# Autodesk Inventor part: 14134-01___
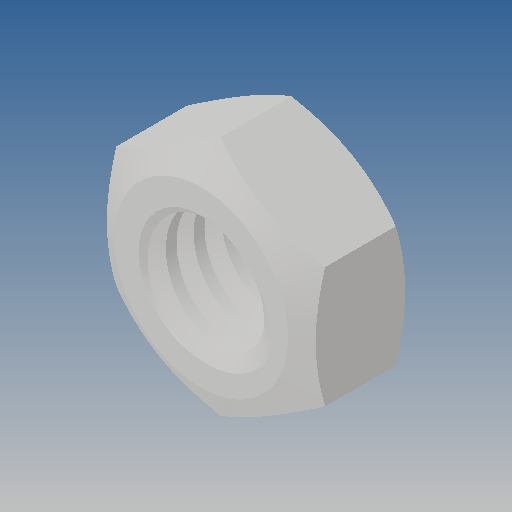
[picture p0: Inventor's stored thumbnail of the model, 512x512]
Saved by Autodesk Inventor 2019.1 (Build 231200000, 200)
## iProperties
Created: 2010-06
Part Number: 14134-01___
Material: Ogólny
Document SubType Name: Modeling
Designer: CADENGINEERING4
Density: 1 g/cm^3
Appearance: Domyślna
Author: CADENGINEERING4
Revision Number: ANY
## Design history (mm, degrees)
feature "NONE"
node "Bryła1"
